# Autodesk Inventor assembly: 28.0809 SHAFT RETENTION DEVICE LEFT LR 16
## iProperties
Created: 2009-01
Part Number: 28.0809 SHAFT RETENTION DEVICE LEFT LR 16
Document SubType Name: Assembly
Designer: Administrator
Author: Administrator
